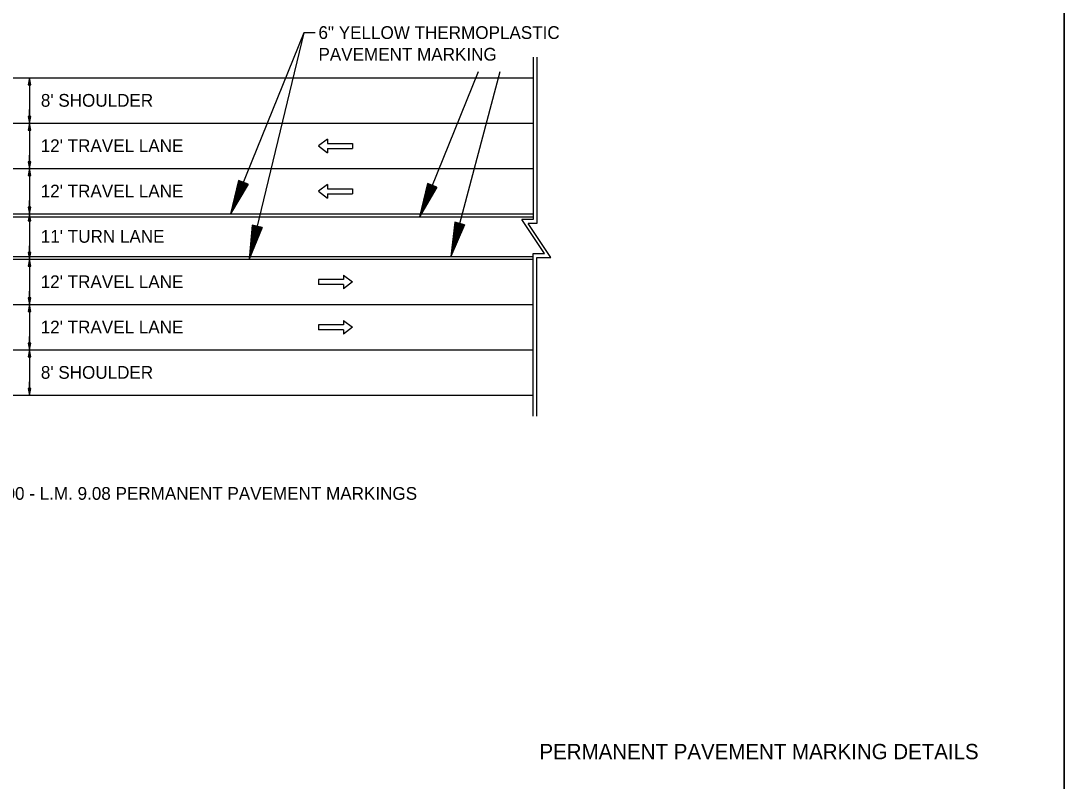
# Model space of a CAD drawing. Extents: x 1373096 to 1373266, y 381130 to 381790.
# Drawn here: x 1373174 to 1373266, y 381462.1 to 381529.2 of the extents above; entities that cross this region are included whole.
import ezdxf

# ---------------------------------------------------------------- set-up
doc = ezdxf.new("R2010")
doc.units = 0
for name, color, linetype in [('Default', 7, 'Continuous'), ('DSN_DRFT_Junk-No-Plot', 7, 'Continuous'), ('R_Border Notes', 7, 'Continuous'), ('R_Draft', 7, 'Continuous')]:
    doc.layers.add(name, color=color, linetype=linetype)

msp = doc.modelspace()

# ---------------------------------------------------------------- linework, layer by layer
at = {"layer": 'Default'}
for p, q in [((1373198.936, 381528.092), (1373192.496, 381512.128)), ((1373198.936, 381528.092), (1373194.121, 381508.128)), ((1373199.936, 381528.092), (1373198.936, 381528.092)), ((1373219.169, 381525.965), (1373219.169, 381511.628)), ((1373219.502, 381525.965), (1373219.502, 381511.295)), ((1373214.305, 381524.664), (1373209.147, 381511.878)), ((1373216.238, 381524.671), (1373211.913, 381508.378)), ((1373201.021, 381518.728), (1373200.242, 381518.128)), ((1373200.242, 381518.128), (1373201.021, 381517.528)), ((1373201.021, 381518.728), (1373201.021, 381518.353)), ((1373201.021, 381518.353), (1373203.227, 381518.353)), ((1373201.021, 381517.903), (1373203.227, 381517.903)), ((1373201.021, 381517.903), (1373201.021, 381517.528)), ((1373203.227, 381518.353), (1373203.227, 381517.903)), ((1373193.201, 381515.078), (1373192.496, 381512.128)), ((1373194.036, 381514.742), (1373193.201, 381515.078)), ((1373194.036, 381514.742), (1373192.496, 381512.128)), ((1373193.271, 381515.05), (1373192.684, 381512.593)), ((1373193.966, 381514.77), (1373192.684, 381512.593)), ((1373193.342, 381515.022), (1373192.877, 381513.071)), ((1373193.895, 381514.798), (1373192.877, 381513.071)), ((1373193.411, 381514.994), (1373193.064, 381513.534)), ((1373193.826, 381514.826), (1373193.064, 381513.534)), ((1373193.482, 381514.965), (1373193.254, 381514.006)), ((1373193.754, 381514.856), (1373193.254, 381514.006)), ((1373193.553, 381514.936), (1373193.441, 381514.47)), ((1373193.684, 381514.884), (1373193.441, 381514.47)), ((1373201.021, 381514.728), (1373200.242, 381514.128)), ((1373201.021, 381514.728), (1373201.021, 381514.353)), ((1373201.021, 381514.353), (1373203.227, 381514.353)), ((1373203.227, 381514.353), (1373203.227, 381513.903)), ((1373209.852, 381514.828), (1373209.147, 381511.878)), ((1373210.687, 381514.492), (1373209.147, 381511.878)), ((1373209.922, 381514.8), (1373209.334, 381512.343)), ((1373210.617, 381514.52), (1373209.334, 381512.343)), ((1373209.993, 381514.772), (1373209.528, 381512.821)), ((1373210.546, 381514.548), (1373209.528, 381512.821)), ((1373210.062, 381514.744), (1373209.714, 381513.284)), ((1373210.477, 381514.576), (1373209.714, 381513.284)), ((1373210.687, 381514.492), (1373209.852, 381514.828)), ((1373210.133, 381514.715), (1373209.905, 381513.756)), ((1373210.404, 381514.606), (1373209.905, 381513.756)), ((1373210.204, 381514.686), (1373210.092, 381514.22)), ((1373210.335, 381514.634), (1373210.092, 381514.22)), ((1373200.242, 381514.128), (1373201.021, 381513.528)), ((1373201.021, 381513.903), (1373203.227, 381513.903)), ((1373201.021, 381513.903), (1373201.021, 381513.528)), ((1373212.248, 381511.393), (1373211.913, 381508.378)), ((1373213.118, 381511.162), (1373212.248, 381511.393)), ((1373219.169, 381511.628), (1373218.169, 381511.628)), ((1373220.169, 381508.628), (1373218.169, 381511.628)), ((1373194.387, 381511.15), (1373194.121, 381508.128)), ((1373195.262, 381510.939), (1373194.121, 381508.128)), ((1373194.46, 381511.132), (1373194.239, 381508.615)), ((1373195.189, 381510.956), (1373194.239, 381508.615)), ((1373194.535, 381511.114), (1373194.36, 381509.117)), ((1373195.115, 381510.974), (1373194.36, 381509.117)), ((1373195.262, 381510.939), (1373194.387, 381511.15)), ((1373194.608, 381511.097), (1373194.477, 381509.602)), ((1373195.042, 381510.992), (1373194.477, 381509.602)), ((1373194.682, 381511.079), (1373194.596, 381510.096)), ((1373194.966, 381511.01), (1373194.596, 381510.096)), ((1373194.756, 381511.061), (1373194.714, 381510.583)), ((1373194.893, 381511.028), (1373194.714, 381510.583)), ((1373213.118, 381511.162), (1373211.913, 381508.378)), ((1373212.32, 381511.374), (1373212.042, 381508.862)), ((1373213.045, 381511.181), (1373212.042, 381508.862)), ((1373212.394, 381511.354), (1373212.174, 381509.361)), ((1373212.971, 381511.201), (1373212.174, 381509.361)), ((1373212.467, 381511.335), (1373212.302, 381509.844)), ((1373212.899, 381511.22), (1373212.302, 381509.844)), ((1373212.541, 381511.315), (1373212.433, 381510.335)), ((1373212.823, 381511.24), (1373212.433, 381510.335)), ((1373212.615, 381511.296), (1373212.561, 381510.819)), ((1373212.751, 381511.259), (1373212.561, 381510.819)), ((1373220.725, 381508.295), (1373218.725, 381511.295)), ((1373219.502, 381511.295), (1373218.725, 381511.295)), ((1373219.169, 381494.291), (1373219.169, 381508.628)), ((1373219.169, 381508.628), (1373220.169, 381508.628)), ((1373219.502, 381494.291), (1373219.502, 381508.295)), ((1373219.502, 381508.295), (1373220.725, 381508.295)), ((1373202.449, 381506.353), (1373200.242, 381506.353)), ((1373200.242, 381506.353), (1373200.242, 381505.903)), ((1373202.449, 381505.903), (1373200.242, 381505.903)), ((1373202.449, 381506.728), (1373202.449, 381506.353)), ((1373202.449, 381506.728), (1373203.227, 381506.128)), ((1373203.227, 381506.128), (1373202.449, 381505.528)), ((1373202.449, 381505.903), (1373202.449, 381505.528)), ((1373202.449, 381502.353), (1373200.242, 381502.353)), ((1373200.242, 381502.353), (1373200.242, 381501.903)), ((1373202.449, 381502.728), (1373202.449, 381502.353)), ((1373202.449, 381502.728), (1373203.227, 381502.128)), ((1373202.449, 381501.903), (1373200.242, 381501.903)), ((1373203.227, 381502.128), (1373202.449, 381501.528)), ((1373202.449, 381501.903), (1373202.449, 381501.528))]:
    msp.add_line(p, q, dxfattribs=at)
msp.add_lwpolyline([(1373095.974, 381570.174), (1373095.974, 381460.174), (1373265.974, 381460.174), (1373265.974, 381570.174)], close=True, dxfattribs=at)
at = {"layer": 'DSN_DRFT_Junk-No-Plot'}
msp.add_line((1373174.763, 381524.128), (1373174.763, 381496.128), dxfattribs=at)
for points in [[(1373095.974, 381570.174), (1373265.974, 381570.174), (1373265.974, 381460.174), (1373095.974, 381460.174)], [(1373095.974, 381570.174), (1373095.974, 381460.174), (1373265.974, 381460.174), (1373265.974, 381570.174)]]:
    msp.add_lwpolyline(points, close=True, dxfattribs=at)
for points in [[(1373174.763, 381524.128), (1373174.643, 381523.528), (1373174.883, 381523.528), (1373174.763, 381524.128), (1373174.763, 381522.928)], [(1373174.763, 381520.128), (1373174.883, 381520.728), (1373174.643, 381520.728), (1373174.763, 381520.128), (1373174.763, 381521.328)], [(1373174.763, 381520.128), (1373174.643, 381519.528), (1373174.883, 381519.528), (1373174.763, 381520.128), (1373174.763, 381518.928)], [(1373174.763, 381516.128), (1373174.883, 381516.728), (1373174.643, 381516.728), (1373174.763, 381516.128), (1373174.763, 381517.328)], [(1373174.763, 381516.128), (1373174.643, 381515.528), (1373174.883, 381515.528), (1373174.763, 381516.128), (1373174.763, 381514.928)], [(1373174.763, 381512.128), (1373174.883, 381512.728), (1373174.643, 381512.728), (1373174.763, 381512.128), (1373174.763, 381513.328)], [(1373174.763, 381512.128), (1373174.643, 381511.528), (1373174.883, 381511.528), (1373174.763, 381512.128), (1373174.763, 381510.928)], [(1373174.763, 381508.128), (1373174.883, 381508.728), (1373174.643, 381508.728), (1373174.763, 381508.128), (1373174.763, 381509.328)], [(1373174.763, 381508.128), (1373174.643, 381507.528), (1373174.883, 381507.528), (1373174.763, 381508.128), (1373174.763, 381506.928)], [(1373174.763, 381504.128), (1373174.883, 381504.728), (1373174.643, 381504.728), (1373174.763, 381504.128), (1373174.763, 381505.328)], [(1373174.763, 381504.128), (1373174.643, 381503.528), (1373174.883, 381503.528), (1373174.763, 381504.128), (1373174.763, 381502.928)], [(1373174.763, 381500.128), (1373174.883, 381500.728), (1373174.643, 381500.728), (1373174.763, 381500.128), (1373174.763, 381501.328)], [(1373174.763, 381500.128), (1373174.643, 381499.528), (1373174.883, 381499.528), (1373174.763, 381500.128), (1373174.763, 381498.928)], [(1373174.763, 381496.128), (1373174.883, 381496.728), (1373174.643, 381496.728), (1373174.763, 381496.128), (1373174.763, 381497.328)]]:
    msp.add_lwpolyline(points, dxfattribs=at)
at = {"layer": 'R_Draft'}
for p, q in [((1373142.778, 381524.128), (1373219.169, 381524.128)), ((1373142.778, 381520.128), (1373219.169, 381520.128)), ((1373142.778, 381516.128), (1373219.169, 381516.128)), ((1373142.778, 381512.128), (1373219.169, 381512.128)), ((1373142.778, 381511.878), (1373219.169, 381511.878)), ((1373142.778, 381508.378), (1373219.169, 381508.378)), ((1373142.778, 381508.128), (1373219.169, 381508.128)), ((1373142.778, 381504.128), (1373219.169, 381504.128)), ((1373142.778, 381500.128), (1373219.169, 381500.128)), ((1373142.778, 381496.128), (1373219.169, 381496.128))]:
    msp.add_line(p, q, dxfattribs=at)

# ---------------------------------------------------------------- texts
at = {"layer": 'Default'}
for s, p in [('6" YELLOW THERMOPLASTIC', (1373200.237, 381527.566)), ('PAVEMENT MARKING', (1373200.237, 381525.653))]:
    msp.add_text(s, height=1.125, dxfattribs=at).set_placement(p)
at = {"layer": 'R_Border Notes'}
msp.add_text('PERMANENT PAVEMENT MARKING DETAILS', height=1.35, dxfattribs=at).set_placement((1373219.719, 381464.024))
at = {"layer": 'R_Draft'}
for s, p in [("8' SHOULDER", (1373175.762, 381521.586)), ("12' TRAVEL LANE", (1373175.752, 381517.586)), ("12' TRAVEL LANE", (1373175.752, 381513.586)), ("11' TURN LANE", (1373175.76, 381509.586)), ("12' TRAVEL LANE", (1373175.752, 381505.586)), ("12' TRAVEL LANE", (1373175.752, 381501.586)), ("8' SHOULDER", (1373175.762, 381497.586)), ('HWY. 167 SECTION 18 L.M. 8.00 - L.M. 9.08 PERMANENT PAVEMENT MARKINGS', (1373151.582, 381486.91))]:
    msp.add_text(s, height=1.125, dxfattribs=at).set_placement(p)

doc.saveas('drawing.dxf')
